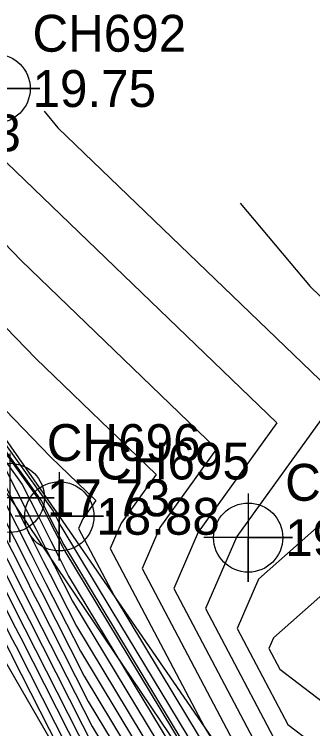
# Model space of a CAD drawing. Extents: x 2531902 to 2533249, y 715219 to 716099.
# Drawn here: x 2532662.18 to 2532682.38, y 715724.93 to 715773.38 of the extents above; entities that cross this region are included whole.
import ezdxf

# ---------------------------------------------------------------- set-up
doc = ezdxf.new("R2010")
doc.units = 0
for name, color, linetype in [('DTM Contours Major', 7, 'Continuous'), ('DTM Contours Minor', 7, 'Continuous'), ('Exist DTM Breakline', 7, 'Continuous'), ('Exist DTM Breakline Cogo Elevation', 7, 'Continuous'), ('Exist DTM Breakline Cogo Number', 7, 'Continuous'), ('Exist DTM Breakline Cogo Point CELL', 7, 'Continuous'), ('Exist DTM Breakline Underwater', 7, 'Continuous'), ('Exist DTM QL2 LIDAR Elevation Point', 7, 'Continuous'), ('Exist DTM Regular Point CELL', 7, 'Continuous'), ('Exist DTM Regular Point Cogo Elevation', 7, 'Continuous'), ('Exist DTM Regular Point Cogo Number', 7, 'Continuous'), ('Exist Hydro Stream or Body of Water', 7, 'Continuous'), ('Scratch_Level_2', 7, 'Continuous')]:
    doc.layers.add(name, color=color, linetype=linetype)

msp = doc.modelspace()

# ---------------------------------------------------------------- linework, layer by layer
at = {"layer": 'DTM Contours Major'}
for points in [[(2532649.633, 715761.418), (2532652.853, 715756.928), (2532656.657, 715751.625), (2532664.623, 715743.377), (2532667.706, 715740.404), (2532666.809, 715739.156), (2532666.528, 715738.511), (2532668.94, 715733.933), (2532672.977, 715727.234), (2532680.368, 715714.969), (2532681.544, 715712.977), (2532683.635, 715709.501), (2532686.333, 715705.014), (2532690.675, 715692.977), (2532694.04, 715683.649), (2532695.571, 715678.45), (2532696.057, 715676.798), (2532696.595, 715675.745)], [(2532677.458, 715760.578), (2532682.204, 715754.915), (2532688.134, 715749.197), (2532685.284, 715745.235), (2532682.849, 715738.741), (2532678.72, 715735.084), (2532677.262, 715731.73), (2532680.691, 715725.22), (2532688.706, 715719.105), (2532688.324, 715710.996), (2532689.533, 715708.674), (2532694.988, 715708.084), (2532700, 715700.698), (2532708.045, 715701.955), (2532710, 715701.824), (2532713.335, 715700), (2532713.757, 715696.243), (2532714.581, 715693.241)], [(2532648.836, 715759.695), (2532660.585, 715743.315), (2532663.46, 715737.646), (2532664.163, 715736.258), (2532664.6, 715735.397), (2532666.384, 715731.88), (2532676.095, 715715.765), (2532678.43, 715711.81), (2532679.978, 715709.189), (2532683.024, 715704.123), (2532687.927, 715690.534), (2532690.367, 715682.244), (2532692.007, 715676.673), (2532692.528, 715674.904), (2532693.303, 715672.271), (2532693.837, 715671.226)], [(2532648.039, 715757.973), (2532655.303, 715747.844), (2532662.601, 715733.455), (2532662.956, 715732.756), (2532663.176, 715732.322), (2532667.705, 715723.393), (2532671.821, 715716.561), (2532677.749, 715706.522), (2532678.412, 715705.4), (2532679.715, 715703.233), (2532681.813, 715697.419), (2532688.008, 715676.376), (2532688.443, 715674.897), (2532688.581, 715674.428), (2532690.418, 715668.187)]]:
    msp.add_lwpolyline(points, dxfattribs=at)
at = {"layer": 'DTM Contours Minor'}
for points in [[(2532658.323, 715766.785), (2532661.653, 715763.337), (2532679.963, 715745.68), (2532674.634, 715738.272), (2532672.968, 715734.443), (2532681.775, 715717.727), (2532684.122, 715715.936)], [(2532664.191, 715766.803), (2532665.133, 715765.68), (2532684.049, 715747.438), (2532677.242, 715737.977), (2532675.115, 715733.086), (2532681.233, 715721.473), (2532686.414, 715717.521)], [(2532654.889, 715764.712), (2532662.643, 715756.684), (2532675.877, 715743.921), (2532672.025, 715738.567), (2532670.822, 715735.799), (2532681.174, 715716.15), (2532681.493, 715715.62), (2532682.077, 715714.65), (2532682.17, 715714.493), (2532686.651, 715707.042)], [(2532651.454, 715762.64), (2532663.633, 715750.031), (2532671.792, 715742.162), (2532669.417, 715738.861), (2532668.675, 715737.155), (2532675.057, 715725.042), (2532677.235, 715721.427), (2532681.222, 715714.809), (2532681.857, 715713.735), (2532685.143, 715708.271)], [(2532649.473, 715761.074), (2532659.233, 715747.467), (2532664.81, 715739.691), (2532665.129, 715739.06), (2532665.328, 715738.669), (2532668.719, 715733.041), (2532679.513, 715715.128), (2532681.23, 715712.22), (2532682.127, 715710.73), (2532685.671, 715704.836)], [(2532649.314, 715760.729), (2532663.753, 715740.597), (2532663.975, 715740.161), (2532664.888, 715738.36), (2532665.455, 715737.242), (2532665.592, 715736.972), (2532678.659, 715715.287), (2532678.838, 715714.983), (2532680.917, 715711.462), (2532685.01, 715704.658)], [(2532648.995, 715760.04), (2532661.641, 715742.409), (2532663.631, 715738.484), (2532664.405, 715736.959), (2532664.885, 715736.012), (2532666.12, 715733.577), (2532676.949, 715715.606), (2532678.566, 715712.868), (2532680.291, 715709.947), (2532683.686, 715704.302)], [(2532649.155, 715760.385), (2532662.697, 715741.503), (2532663.803, 715739.323), (2532664.646, 715737.659), (2532665.17, 715736.627), (2532665.856, 715735.275), (2532677.804, 715715.447), (2532678.702, 715713.925), (2532680.604, 715710.704), (2532684.348, 715704.48)], [(2532648.517, 715759.006), (2532658.472, 715745.126), (2532663.116, 715735.97), (2532663.68, 715734.857), (2532664.031, 715734.167), (2532666.912, 715728.485), (2532674.385, 715716.084), (2532678.158, 715709.695), (2532679.351, 715707.673), (2532681.701, 715703.767), (2532685.481, 715693.288)], [(2532648.676, 715759.351), (2532659.528, 715744.221), (2532663.288, 715736.808), (2532663.922, 715735.558), (2532664.315, 715734.782), (2532666.648, 715730.183), (2532675.24, 715715.924), (2532678.294, 715710.752), (2532679.664, 715708.431), (2532682.362, 715703.945), (2532686.704, 715691.911)], [(2532648.358, 715758.662), (2532657.416, 715746.032), (2532662.945, 715735.132), (2532663.439, 715734.157), (2532663.746, 715733.552), (2532667.176, 715726.788), (2532673.531, 715716.243), (2532678.022, 715708.637), (2532679.038, 715706.916), (2532681.039, 715703.589), (2532684.258, 715694.665)], [(2532648.198, 715758.317), (2532656.36, 715746.938), (2532662.773, 715734.293), (2532663.198, 715733.456), (2532663.461, 715732.937), (2532667.44, 715725.091), (2532672.676, 715716.402), (2532677.886, 715707.579), (2532678.725, 715706.158), (2532680.377, 715703.411), (2532683.035, 715696.042)], [(2532647.88, 715757.628), (2532654.247, 715748.75), (2532662.43, 715732.617), (2532662.715, 715732.055), (2532662.891, 715731.707), (2532667.969, 715721.696), (2532670.967, 715716.721), (2532677.613, 715705.464), (2532678.098, 715704.643), (2532679.053, 715703.055), (2532680.59, 715698.796), (2532687.536, 715675.203)], [(2532647.72, 715757.283), (2532653.191, 715749.656), (2532662.258, 715731.779), (2532662.473, 715731.355), (2532662.606, 715731.092), (2532668.233, 715719.999), (2532670.112, 715716.88), (2532677.477, 715704.406), (2532677.785, 715703.885), (2532678.391, 715702.877), (2532679.367, 715700.173), (2532686.165, 715677.082)], [(2532641.792, 715749.059), (2532642.611, 715747.522), (2532653.524, 715727.048), (2532655.47, 715722.96), (2532655.53, 715722.852), (2532658.24, 715717.905), (2532658.527, 715717.303), (2532658.762, 715716.89), (2532661.398, 715712.269), (2532666.133, 715706.603), (2532664.574, 715714.399), (2532665.75, 715717.772), (2532667.089, 715719.901), (2532662.037, 715729.861), (2532661.99, 715729.954), (2532661.915, 715730.102), (2532651.078, 715751.468), (2532647.402, 715756.594)], [(2532668.497, 715718.301), (2532662.322, 715730.477), (2532662.232, 715730.654), (2532662.086, 715730.941), (2532652.135, 715750.562), (2532647.561, 715756.939)], [(2532689.717, 715739.95), (2532679.724, 715731.098), (2532679.408, 715730.374), (2532680.149, 715728.967), (2532683.875, 715726.125)]]:
    msp.add_lwpolyline(points, dxfattribs=at)
at = {"layer": 'Exist DTM Breakline'}
msp.add_lwpolyline([(2532649.711, 715761.588), (2532665.224, 715739.335), (2532688.443, 715705.582), (2532697.711, 715679.516), (2532703.673, 715665.533), (2532716.286, 715652.801)], dxfattribs=at)
at = {"layer": 'Exist DTM Breakline Cogo Point CELL'}
for points in [[(2532661.875, 715743.587), (2532661.875, 715737.587), (2532661.875, 715740.587), (2532664.875, 715740.587), (2532658.875, 715740.587)], [(2532665.224, 715742.335), (2532665.224, 715736.335), (2532665.224, 715739.335), (2532668.224, 715739.335), (2532662.224, 715739.335)]]:
    msp.add_lwpolyline(points, dxfattribs=at)
for centre in [(2532661.875, 715740.587), (2532665.224, 715739.335)]:
    msp.add_circle(centre, 2.344, dxfattribs=at)
at = {"layer": 'Exist DTM Breakline Underwater'}
msp.add_lwpolyline([(2532646.748, 715755.182), (2532668.676, 715717.147), (2532677.241, 715702.567), (2532689.842, 715666.582), (2532701.723, 715652.924), (2532713.134, 715647.155), (2532737.59, 715643.253), (2532756.176, 715636.457), (2532783.406, 715639.452), (2532803.254, 715642.171), (2532813.801, 715644.931), (2532836.277, 715651.081), (2532865.559, 715653.815), (2532885.826, 715645.124), (2532889.946, 715643.683), (2532906.865, 715630.423), (2532927.34, 715618.228), (2532957.965, 715607.729), (2532978.566, 715598.571), (2533001.091, 715586.568), (2533028.19, 715572.821)], dxfattribs=at)
at = {"layer": 'Exist DTM QL2 LIDAR Elevation Point'}
msp.add_line((2532680, 715730), (2532680, 715730), dxfattribs=at)
at = {"layer": 'Exist DTM Regular Point CELL'}
for points in [[(2532660.908, 715771.344), (2532660.908, 715765.344), (2532660.908, 715768.344), (2532663.908, 715768.344), (2532657.908, 715768.344)], [(2532678.014, 715740.89), (2532678.014, 715734.89), (2532678.014, 715737.89), (2532681.014, 715737.89), (2532675.014, 715737.89)]]:
    msp.add_lwpolyline(points, dxfattribs=at)
for centre in [(2532660.908, 715768.344), (2532678.014, 715737.89)]:
    msp.add_circle(centre, 2.344, dxfattribs=at)
at = {"layer": 'Exist Hydro Stream or Body of Water'}
msp.add_lwpolyline([(2532649.354, 715760.815), (2532664.017, 715740.37), (2532664.948, 715738.535), (2532665.526, 715737.396), (2532678.872, 715715.247), (2532680.996, 715711.651), (2532685.175, 715704.702), (2532691.901, 715686.059), (2532694.324, 715677.828), (2532695.093, 715675.214), (2532699.89, 715665.82), (2532703.016, 715661.283), (2532714.635, 715652.814), (2532715.929, 715652.16), (2532727.227, 715650.963), (2532730.055, 715650.803), (2532751.801, 715642.405), (2532753.898, 715641.752), (2532766.592, 715639.773), (2532767.187, 715639.811), (2532779.493, 715644.52), (2532786.898, 715645.569), (2532790.115, 715646.495), (2532806.64, 715649.775)], dxfattribs=at)
at = {"layer": 'Scratch_Level_2'}
msp.add_lwpolyline([(2532646.331, 715760.978), (2532661.875, 715740.587), (2532684.759, 715706.615), (2532696, 715677.679), (2532701.748, 715665.356), (2532714.118, 715649.677)], dxfattribs=at)

# ---------------------------------------------------------------- texts
at = {"layer": 'Exist DTM Breakline Cogo Elevation'}
for s, p in [('17.73', (2532664.375, 715739.337)), ('18.88', (2532667.724, 715738.085))]:
    msp.add_text(s, height=2.5, dxfattribs=at).set_placement(p)
at = {"layer": 'Exist DTM Breakline Cogo Number'}
for s, p in [('CH693', (2532652.211, 715764.088)), ('CH696', (2532664.375, 715743.087)), ('CH695', (2532667.724, 715741.835))]:
    msp.add_text(s, height=2.5, dxfattribs=at).set_placement(p)
at = {"layer": 'Exist DTM Regular Point Cogo Elevation'}
for s, p in [('19.75', (2532663.408, 715767.094)), ('19.86', (2532680.514, 715736.64))]:
    msp.add_text(s, height=2.5, dxfattribs=at).set_placement(p)
at = {"layer": 'Exist DTM Regular Point Cogo Number'}
for s, p in [('CH692', (2532663.408, 715770.844)), ('CH697', (2532680.514, 715740.39))]:
    msp.add_text(s, height=2.5, dxfattribs=at).set_placement(p)

doc.saveas('drawing.dxf')
